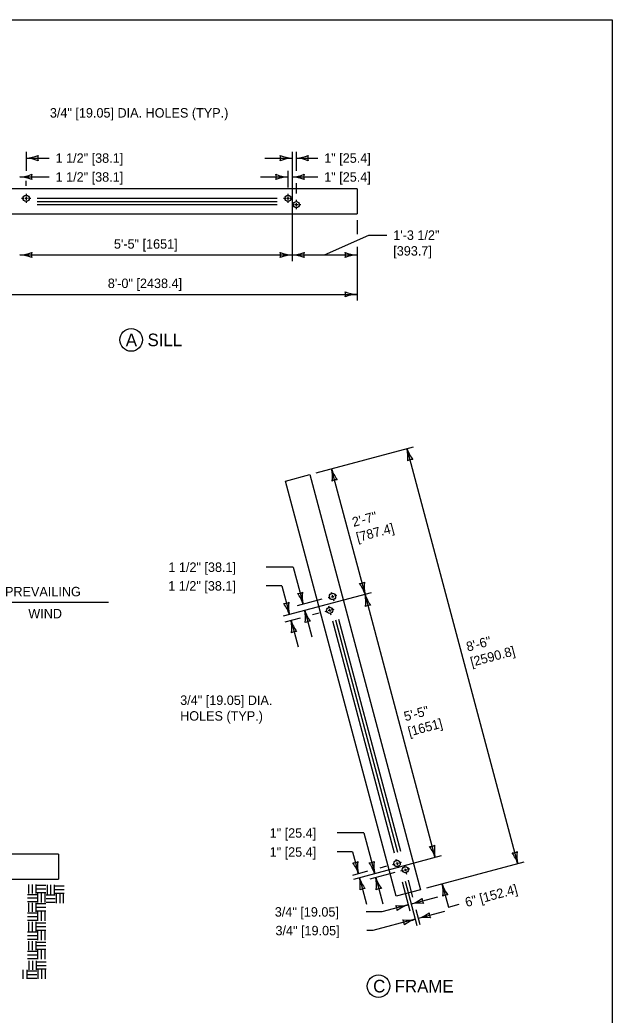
# Model space of a CAD drawing. Extents: x 49991 to 79985, y 47703 to 60542.
# Drawn here: x 50012.99 to 50016.75, y 49992.68 to 49999 of the extents above; entities that cross this region are included whole.
import ezdxf

# ---------------------------------------------------------------- set-up
doc = ezdxf.new("R2010")
doc.units = 0
for name, color, linetype in [('Level 1', 7, 'Continuous'), ('Level 2', 7, 'Continuous'), ('Level 3', 7, 'Continuous'), ('Level 5', 7, 'Continuous')]:
    doc.layers.add(name, color=color, linetype=linetype)

msp = doc.modelspace()

# ---------------------------------------------------------------- linework, layer by layer
at = {"layer": 'Level 1'}
for p, q in [((50015.1288, 49997.926), (50012.5733, 49997.926)), ((50015.1288, 49997.926), (50015.1288, 49997.7663)), ((50012.5733, 49997.7663), (50015.1288, 49997.7663)), ((50014.6741, 49996.0696), (50014.8287, 49996.1108)), ((50015.3771, 49993.4321), (50014.6741, 49996.0696)), ((50014.8287, 49996.1108), (50015.5317, 49993.4733)), ((50013.2307, 49993.7005), (50012.8762, 49993.7005)), ((50013.2307, 49993.7005), (50013.2307, 49993.5408)), ((50012.9191, 49993.5408), (50013.2307, 49993.5408)), ((50013.0411, 49993.5078), (50013.0411, 49993.45)), ((50013.0643, 49993.5078), (50013.0643, 49993.45)), ((50013.0874, 49993.5078), (50013.0874, 49993.45)), ((50013.0928, 49993.5024), (50013.1506, 49993.5024)), ((50013.0928, 49993.4793), (50013.1506, 49993.4793)), ((50013.1583, 49993.5044), (50013.1583, 49993.4466)), ((50013.1815, 49993.5044), (50013.1815, 49993.4466)), ((50013.2046, 49993.5044), (50013.2046, 49993.4466)), ((50013.21, 49993.499), (50013.2678, 49993.499)), ((50013.21, 49993.4759), (50013.2678, 49993.4759)), ((50015.5317, 49993.4733), (50015.3771, 49993.4321)), ((50013.0349, 49993.4446), (50013.0928, 49993.4446)), ((50013.0349, 49993.4215), (50013.0928, 49993.4215)), ((50013.0349, 49993.3983), (50013.0928, 49993.3983)), ((50013.0928, 49993.4562), (50013.1506, 49993.4562)), ((50013.0985, 49993.4504), (50013.0985, 49993.3926)), ((50013.1217, 49993.4504), (50013.1217, 49993.3926)), ((50013.1448, 49993.4504), (50013.1448, 49993.3926)), ((50013.1521, 49993.4412), (50013.21, 49993.4412)), ((50013.1521, 49993.4181), (50013.21, 49993.4181)), ((50013.21, 49993.4528), (50013.2678, 49993.4528)), ((50013.2157, 49993.447), (50013.2157, 49993.3892)), ((50013.2389, 49993.447), (50013.2389, 49993.3892)), ((50013.262, 49993.447), (50013.262, 49993.3892)), ((50013.0411, 49993.3911), (50013.0411, 49993.3333)), ((50013.0643, 49993.3911), (50013.0643, 49993.3333)), ((50013.0874, 49993.3911), (50013.0874, 49993.3333)), ((50013.0928, 49993.3857), (50013.1506, 49993.3857)), ((50013.0928, 49993.3626), (50013.1506, 49993.3626)), ((50013.0928, 49993.3395), (50013.1506, 49993.3395)), ((50013.0985, 49993.3337), (50013.0985, 49993.2759)), ((50013.1217, 49993.3337), (50013.1217, 49993.2759)), ((50013.1448, 49993.3337), (50013.1448, 49993.2759)), ((50013.1521, 49993.3949), (50013.21, 49993.3949)), ((50013.0349, 49993.3279), (50013.0928, 49993.3279)), ((50013.0349, 49993.3048), (50013.0928, 49993.3048)), ((50013.0349, 49993.2816), (50013.0928, 49993.2816)), ((50013.0411, 49993.2693), (50013.0411, 49993.2115)), ((50013.0643, 49993.2693), (50013.0643, 49993.2115)), ((50013.0874, 49993.2693), (50013.0874, 49993.2115)), ((50013.0349, 49993.2061), (50013.0928, 49993.2061)), ((50013.0928, 49993.2639), (50013.1506, 49993.2639)), ((50013.0928, 49993.2408), (50013.1506, 49993.2408)), ((50013.0928, 49993.2177), (50013.1506, 49993.2177)), ((50013.0985, 49993.2119), (50013.0985, 49993.1541)), ((50013.1217, 49993.2119), (50013.1217, 49993.1541)), ((50013.1448, 49993.2119), (50013.1448, 49993.1541)), ((50013.0349, 49993.183), (50013.0928, 49993.183)), ((50013.0349, 49993.1598), (50013.0928, 49993.1598)), ((50013.0411, 49993.1474), (50013.0411, 49993.0896)), ((50013.0643, 49993.1474), (50013.0643, 49993.0896)), ((50013.0874, 49993.1474), (50013.0874, 49993.0896)), ((50013.0349, 49993.0842), (50013.0928, 49993.0842)), ((50013.0928, 49993.142), (50013.1506, 49993.142)), ((50013.0928, 49993.1189), (50013.1506, 49993.1189)), ((50013.0928, 49993.0958), (50013.1506, 49993.0958)), ((50013.0985, 49993.09), (50013.0985, 49993.0322)), ((50013.1217, 49993.09), (50013.1217, 49993.0322)), ((50013.1448, 49993.09), (50013.1448, 49993.0322)), ((50013.0349, 49993.0611), (50013.0928, 49993.0611)), ((50013.0349, 49993.0379), (50013.0928, 49993.0379)), ((50013.0428, 49993.0222), (50013.0428, 49992.9644)), ((50013.066, 49993.0222), (50013.066, 49992.9644)), ((50013.0891, 49993.0222), (50013.0891, 49992.9644)), ((50013.0945, 49993.0168), (50013.1523, 49993.0168)), ((50013.0053, 49992.9648), (50013.0053, 49992.907)), ((50013.0295, 49992.9648), (50013.0295, 49992.907)), ((50013.0366, 49992.959), (50013.0945, 49992.959)), ((50013.0945, 49992.9937), (50013.1523, 49992.9937)), ((50013.0945, 49992.9706), (50013.1523, 49992.9706)), ((50013.1002, 49992.9648), (50013.1002, 49992.907)), ((50013.1234, 49992.9648), (50013.1234, 49992.907)), ((50013.1465, 49992.9648), (50013.1465, 49992.907)), ((50013.0366, 49992.9359), (50013.0945, 49992.9359)), ((50013.0366, 49992.9127), (50013.0945, 49992.9127))]:
    msp.add_line(p, q, dxfattribs=at)
msp.add_lwpolyline([(49999.3835, 49998.9992), (50016.7501, 49998.9992), (50016.7501, 49987.7988), (49999.3835, 49987.7988)], close=True, dxfattribs=at)
for centre in [(50013.0258, 49997.8661), (50014.6896, 49997.8661), (50014.7428, 49997.8262), (50014.9729, 49995.3368), (50014.9549, 49995.2492), (50015.3835, 49993.6409), (50015.4356, 49993.601)]:
    msp.add_circle(centre, 0.02, dxfattribs=at)
at = {"layer": 'Level 2'}
for centre in [(50013.6932, 49996.9666), (50015.2654, 49992.8617)]:
    msp.add_circle(centre, 0.072, dxfattribs=at)
at = {"layer": 'Level 3'}
for p, q in [((50013.0258, 49998.1615), (50013.0258, 49998.0415)), ((50014.7162, 49998.1615), (50014.7162, 49997.466)), ((50014.7428, 49998.1615), (50014.7428, 49998.0415)), ((50013.0258, 49998.1215), (50013.1727, 49998.1215)), ((50014.5428, 49998.1215), (50014.7162, 49998.1215)), ((50014.7428, 49998.1215), (50014.8802, 49998.1215)), ((50014.6896, 49998.0415), (50014.6896, 49997.9353)), ((50013.0157, 49998.0015), (50013.1727, 49998.0015)), ((50013.0258, 49997.9446), (50013.0258, 49997.977)), ((50014.5162, 49998.0015), (50014.6896, 49998.0015)), ((50014.7162, 49998.0015), (50014.8802, 49998.0015)), ((50014.7428, 49997.9615), (50014.7428, 49997.8955)), ((50013.0951, 49997.8661), (50014.6204, 49997.8661)), ((50013.0951, 49997.8462), (50014.6204, 49997.8462)), ((50013.0951, 49997.8262), (50014.6204, 49997.8262)), ((50015.1288, 49997.7263), (50015.1288, 49997.6386)), ((50012.9859, 49997.506), (50014.7162, 49997.506)), ((50014.7162, 49997.506), (50015.1288, 49997.506)), ((50015.1288, 49997.5586), (50015.1288, 49997.216)), ((50012.5733, 49997.256), (50015.1288, 49997.256)), ((50015.486, 49996.2859), (50014.8674, 49996.1211)), ((50016.1503, 49993.6382), (50015.4473, 49996.2756)), ((50015.1796, 49995.3505), (50014.9672, 49996.1477)), ((50014.7234, 49995.5227), (50014.5519, 49995.5227)), ((50014.7234, 49995.5227), (50014.7862, 49995.2871)), ((50014.651, 49995.4042), (50014.551, 49995.4042)), ((50014.6504, 49995.404), (50014.6988, 49995.2224)), ((50015.2183, 49995.3608), (50014.6602, 49995.2121)), ((50013.5487, 49995.2979), (50012.7056, 49995.2979)), ((50014.906, 49995.319), (50014.7475, 49995.2768)), ((50015.6253, 49993.6785), (50015.1796, 49995.3505)), ((50015.1796, 49995.3505), (50015.1796, 49995.3505)), ((50014.7965, 49995.2484), (50014.8411, 49995.0809)), ((50014.8879, 49995.2314), (50014.8454, 49995.2201)), ((50014.7681, 49995.1995), (50014.6705, 49995.1734)), ((50014.7091, 49995.1837), (50014.7538, 49995.0162)), ((50014.9727, 49995.1823), (50015.3657, 49993.7078)), ((50014.992, 49995.1875), (50015.385, 49993.713)), ((50015.0113, 49995.1926), (50015.4043, 49993.7181)), ((50015.1721, 49993.8345), (50015.0019, 49993.8345)), ((50015.1721, 49993.8345), (50015.241, 49993.576)), ((50015.1009, 49993.7138), (50015.0019, 49993.7138)), ((50015.1009, 49993.7138), (50015.1378, 49993.5754)), ((50015.664, 49993.6888), (50015.1058, 49993.54)), ((50016.1889, 49993.6485), (50015.5703, 49993.4836)), ((50015.1958, 49993.5909), (50015.0991, 49993.5651)), ((50015.3166, 49993.6231), (50015.2731, 49993.6115)), ((50015.1445, 49993.5503), (50015.1891, 49993.3828)), ((50015.3687, 49993.5831), (50015.2092, 49993.5406)), ((50015.2478, 49993.5509), (50015.2925, 49993.3834)), ((50015.4148, 49993.5238), (50015.464, 49993.3392)), ((50015.4341, 49993.5289), (50015.5091, 49993.2476)), ((50015.4534, 49993.5341), (50015.482, 49993.4268)), ((50015.6405, 49993.4277), (50015.473, 49993.383)), ((50015.2861, 49993.3332), (50015.1861, 49993.3332)), ((50015.4536, 49993.3778), (50015.2861, 49993.3332)), ((50015.5026, 49993.3495), (50015.5283, 49993.2531)), ((50015.6855, 49993.3364), (50015.518, 49993.2917)), ((50015.4988, 49993.2863), (50015.2294, 49993.2145)), ((50015.2294, 49993.2145), (50015.1904, 49993.2145))]:
    msp.add_line(p, q, dxfattribs=at)
for points in [[(50014.9225, 49997.506), (50015.203, 49997.6319), (50015.319, 49997.6319)], [(50015.6703, 49993.5103), (50015.7093, 49993.364), (50015.7784, 49993.3824)]]:
    msp.add_lwpolyline(points, dxfattribs=at)
for centre, radius, start, end in [((50013.0143, 49998.3542), 0.233, 272.82731, 292.07716), ((50013.154, 49998.1215), 0.0548, 162.13882, 197.86118), ((50014.7254, 49998.3436), 0.2223, 247.45601, 267.63952), ((50014.588, 49998.1215), 0.0548, 342.13882, 17.86118), ((50014.7313, 49998.3542), 0.233, 272.82731, 292.07716), ((50014.871, 49998.1215), 0.0548, 162.13882, 197.86118), ((50013.0166, 49997.8994), 0.2223, 67.45601, 87.63952), ((50014.7277, 49997.8888), 0.233, 92.82731, 112.07716), ((50014.7336, 49997.8994), 0.2223, 67.45601, 87.63952), ((50012.9744, 49998.2342), 0.233, 272.82731, 292.07716), ((50013.1141, 49998.0015), 0.0548, 162.13882, 197.86118), ((50014.6988, 49998.2236), 0.2223, 247.45601, 267.63952), ((50014.5614, 49998.0015), 0.0548, 342.13882, 17.86118), ((50014.7047, 49998.2342), 0.233, 272.82731, 292.07716), ((50014.8444, 49998.0015), 0.0548, 162.13882, 197.86118), ((50012.9767, 49997.7794), 0.2223, 67.45601, 87.63952), ((50014.7011, 49997.7688), 0.233, 92.82731, 112.07716), ((50014.707, 49997.7794), 0.2223, 67.45601, 87.63952), ((50012.9744, 49997.7387), 0.233, 272.82731, 292.07716), ((50012.9767, 49997.2839), 0.2223, 67.45601, 87.63952), ((50013.1141, 49997.506), 0.0548, 162.13882, 197.86118), ((50014.7254, 49997.7281), 0.2223, 247.45601, 267.63952), ((50014.588, 49997.506), 0.0548, 342.13882, 17.86118), ((50014.7277, 49997.2733), 0.233, 92.82731, 112.07716), ((50014.7047, 49997.7387), 0.233, 272.82731, 292.07716), ((50014.707, 49997.2839), 0.2223, 67.45601, 87.63952), ((50014.8444, 49997.506), 0.0548, 162.13882, 197.86118), ((50015.138, 49997.7281), 0.2223, 247.45601, 267.63952), ((50015.0006, 49997.506), 0.0548, 342.13882, 17.86118), ((50015.1403, 49997.2733), 0.233, 92.82731, 112.07716), ((50015.138, 49997.4781), 0.2223, 247.45601, 267.63952), ((50015.0006, 49997.256), 0.0548, 342.13882, 17.86118), ((50015.1403, 49997.0233), 0.233, 92.82731, 112.07716), ((50015.6596, 49996.3416), 0.2223, 197.27048, 217.45399), ((50015.2195, 49996.2269), 0.233, 352.83284, 12.08269), ((50015.4803, 49996.1517), 0.0548, 87.04882, 122.77118), ((50015.1795, 49996.2137), 0.2223, 197.27048, 217.45399), ((50014.7393, 49996.0989), 0.233, 352.83284, 12.08269), ((50015.0002, 49996.0238), 0.0548, 87.04882, 122.77118), ((50015.1466, 49995.4744), 0.0548, 267.07741, 302.79977), ((50014.9578, 49995.2794), 0.233, 17.7659, 37.01575), ((50015.3966, 49995.399), 0.2223, 172.3946, 192.57811), ((50014.7531, 49995.4109), 0.0548, 267.07741, 302.79977), ((50014.5643, 49995.216), 0.233, 17.7659, 37.01575), ((50015.0032, 49995.3355), 0.2223, 172.3946, 192.57811), ((50014.6658, 49995.3463), 0.0548, 267.07741, 302.79977), ((50014.4769, 49995.1513), 0.233, 17.7659, 37.01575), ((50014.9158, 49995.2708), 0.2223, 172.3946, 192.57811), ((50015.3919, 49995.4165), 0.2223, 197.27048, 217.45399), ((50014.9518, 49995.3018), 0.233, 352.83284, 12.08269), ((50015.0088, 49995.3144), 0.2223, 197.27048, 217.45399), ((50014.5686, 49995.1996), 0.233, 352.83284, 12.08269), ((50015.2126, 49995.2266), 0.0548, 87.04882, 122.77118), ((50014.9214, 49995.2497), 0.2223, 197.27048, 217.45399), ((50014.4813, 49995.135), 0.233, 352.83284, 12.08269), ((50014.8295, 49995.1245), 0.0548, 87.04882, 122.77118), ((50014.7421, 49995.0598), 0.0548, 87.04882, 122.77118), ((50015.5922, 49993.8023), 0.0548, 267.07741, 302.79977), ((50015.4034, 49993.6074), 0.233, 17.7659, 37.01575), ((50015.8423, 49993.7269), 0.2223, 172.3946, 192.57811), ((50016.1172, 49993.7621), 0.0548, 267.07741, 302.79977), ((50016.3673, 49993.6866), 0.2223, 172.3946, 192.57811), ((50015.1047, 49993.6993), 0.0548, 267.07741, 302.79977), ((50015.3548, 49993.6238), 0.2223, 172.3946, 192.57811), ((50015.208, 49993.6999), 0.0548, 267.07741, 302.79977), ((50015.458, 49993.6244), 0.2223, 172.3946, 192.57811), ((50015.9284, 49993.5671), 0.233, 17.7659, 37.01575), ((50014.9159, 49993.5043), 0.233, 17.7659, 37.01575), ((50015.0191, 49993.5049), 0.233, 17.7659, 37.01575), ((50015.3568, 49993.6163), 0.2223, 197.27048, 217.45399), ((50014.9167, 49993.5015), 0.233, 352.83284, 12.08269), ((50015.4601, 49993.6169), 0.2223, 197.27048, 217.45399), ((50015.02, 49993.5022), 0.233, 352.83284, 12.08269), ((50015.1775, 49993.4264), 0.0548, 87.04882, 122.77118), ((50015.2808, 49993.427), 0.0548, 87.04882, 122.77118), ((50015.4533, 49993.462), 0.2223, 352.37632, 12.55983), ((50015.8922, 49993.5813), 0.233, 197.74762, 216.99747), ((50015.407, 49993.5953), 0.2223, 287.27048, 307.45399), ((50015.5969, 49993.416), 0.0548, 177.04882, 212.77118), ((50015.7033, 49993.3864), 0.0548, 87.05913, 122.78149), ((50015.4052, 49993.5948), 0.2223, 262.3946, 282.57811), ((50015.3298, 49993.3448), 0.0548, 357.07741, 32.79977), ((50015.5247, 49993.156), 0.233, 107.7659, 127.01575), ((50015.5217, 49993.1552), 0.233, 82.83284, 102.08269), ((50015.4503, 49993.5033), 0.2223, 262.3946, 282.57811), ((50015.3749, 49993.2532), 0.0548, 357.07741, 32.79977), ((50015.5698, 49993.0644), 0.233, 107.7659, 127.01575), ((50015.452, 49993.504), 0.2223, 287.27048, 307.45399), ((50015.5668, 49993.0639), 0.233, 82.83284, 102.08269), ((50015.6419, 49993.3247), 0.0548, 177.04882, 212.77118)]:
    msp.add_arc(centre, radius, start, end, dxfattribs=at)
at = {"layer": 'Level 5'}
for p, q in [((50013.0258, 49997.8953), (50013.0258, 49997.8803)), ((50014.6896, 49997.8953), (50014.6896, 49997.8803)), ((50012.9966, 49997.8661), (50013.0116, 49997.8661)), ((50013.0166, 49997.8661), (50013.0351, 49997.8661)), ((50013.0258, 49997.8754), (50013.0258, 49997.8569)), ((50013.0258, 49997.8518), (50013.0258, 49997.8368)), ((50013.0401, 49997.8661), (50013.0551, 49997.8661)), ((50014.6604, 49997.8661), (50014.6754, 49997.8661)), ((50014.6804, 49997.8661), (50014.6989, 49997.8661)), ((50014.6896, 49997.8754), (50014.6896, 49997.8569)), ((50014.6896, 49997.8518), (50014.6896, 49997.8368)), ((50014.7039, 49997.8661), (50014.7189, 49997.8661)), ((50014.7136, 49997.8262), (50014.7285, 49997.8262)), ((50014.7336, 49997.8262), (50014.7521, 49997.8262)), ((50014.7428, 49997.8555), (50014.7428, 49997.8405)), ((50014.7428, 49997.8355), (50014.7428, 49997.817)), ((50014.7571, 49997.8262), (50014.772, 49997.8262)), ((50014.7428, 49997.8119), (50014.7428, 49997.7969)), ((50014.9654, 49995.3651), (50014.9692, 49995.3506)), ((50014.9446, 49995.3293), (50014.9591, 49995.3332)), ((50014.964, 49995.3345), (50014.9818, 49995.3392)), ((50014.9705, 49995.3458), (50014.9753, 49995.3279)), ((50014.9766, 49995.3231), (50014.9804, 49995.3086)), ((50014.9867, 49995.3405), (50015.0012, 49995.3444)), ((50014.9266, 49995.2417), (50014.9411, 49995.2456)), ((50014.9459, 49995.2468), (50014.9638, 49995.2516)), ((50014.9473, 49995.2775), (50014.9512, 49995.263)), ((50014.9525, 49995.2582), (50014.9572, 49995.2403)), ((50014.9585, 49995.2355), (50014.9624, 49995.221)), ((50014.9686, 49995.2529), (50014.9831, 49995.2568)), ((50015.376, 49993.6692), (50015.3799, 49993.6547)), ((50015.3811, 49993.6499), (50015.3859, 49993.632)), ((50015.3973, 49993.6446), (50015.4118, 49993.6485)), ((50015.3553, 49993.6334), (50015.3698, 49993.6373)), ((50015.3746, 49993.6385), (50015.3925, 49993.6433)), ((50015.3872, 49993.6272), (50015.3911, 49993.6127)), ((50015.4073, 49993.5934), (50015.4218, 49993.5973)), ((50015.4266, 49993.5986), (50015.4445, 49993.6034)), ((50015.428, 49993.6292), (50015.4319, 49993.6148)), ((50015.4332, 49993.6099), (50015.438, 49993.592)), ((50015.4392, 49993.5872), (50015.4431, 49993.5727)), ((50015.4493, 49993.6047), (50015.4638, 49993.6085))]:
    msp.add_line(p, q, dxfattribs=at)

# ---------------------------------------------------------------- texts
at = {"layer": 'Level 2'}
for s, height, p in [('3/4" [19.05] DIA. HOLES (TYP.)', 0.06, (50013.1765, 49998.3788)), ('1 1/2" [38.1]', 0.06, (50013.2127, 49998.0915)), ('1" [25.4]', 0.06, (50014.9202, 49998.0915)), ('1 1/2" [38.1]', 0.06, (50013.2127, 49997.9715)), ('1" [25.4]', 0.06, (50014.9202, 49997.9715)), ('1\'-3 1/2"', 0.06, (50015.359, 49997.6019)), ('5\'-5" [1651]', 0.06, (50013.5835, 49997.546)), ('[393.7]', 0.06, (50015.359, 49997.5019)), ('8\'-0" [2438.4]', 0.06, (50013.5447, 49997.296)), ('A', 0.08, (50013.6589, 49996.9266)), ('SILL', 0.08, (50013.797, 49996.9266)), ('PREVAILING', 0.06, (50012.8914, 49995.3379)), ('WIND', 0.06, (50013.0396, 49995.1979))]:
    msp.add_text(s, height=height, dxfattribs=at).set_placement(p)
for s, height, rotation, p in [('2\'-7"', 0.06, 14.9228, (50015.1069, 49995.7786)), ('[787.4]', 0.06, 14.9228, (50015.1326, 49995.682)), ('1 1/2" [38.1]', 0.06, 360, (50013.9298, 49995.4927)), ('1 1/2" [38.1]', 0.06, 0, (50013.929, 49995.3742)), ('8\'-6"', 0.06, 14.9228, (50015.8323, 49994.9864)), ('[2590.8]', 0.06, 14.9228, (50015.8581, 49994.8898)), ('3/4" [19.05] DIA.', 0.06, 359.92328, (50014.0047, 49994.6482)), ('HOLES (TYP.)', 0.06, 359.92328, (50014.0045, 49994.5482)), ('5\'-5"', 0.06, 14.9228, (50015.436, 49994.544)), ('[1651]', 0.06, 14.9228, (50015.4617, 49994.4474)), ('1" [25.4]', 0.06, 360, (50014.5733, 49993.8045)), ('1" [25.4]', 0.06, 360, (50014.5733, 49993.6838)), ('6" [152.4]', 0.06, 14.9228, (50015.8248, 49993.3637)), ('3/4" [19.05]', 0.06, 360, (50014.6061, 49993.3032)), ('3/4" [19.05]', 0.06, 360, (50014.6104, 49993.1845)), ('C', 0.08, 359.92328, (50015.2313, 49992.8217)), ('FRAME', 0.08, 359.92328, (50015.3681, 49992.8215))]:
    msp.add_text(s, height=height, rotation=rotation, dxfattribs=at).set_placement(p)

doc.saveas('drawing.dxf')
